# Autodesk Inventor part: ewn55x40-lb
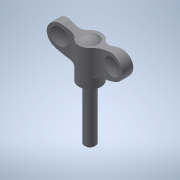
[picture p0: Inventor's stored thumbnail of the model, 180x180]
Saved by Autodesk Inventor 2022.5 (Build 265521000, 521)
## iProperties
Created: 2016-12
Part Number: ewn55x40-lb
Material: 一般
Document SubType Name: Modeling
Designer: imaocorp
Density: 1 g/cm^3
Appearance: 既定
Author: imaocorp
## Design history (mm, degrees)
node "ewn55x40-lb.x_t1"
node "ewn55x40-lb"
node "Base1"
